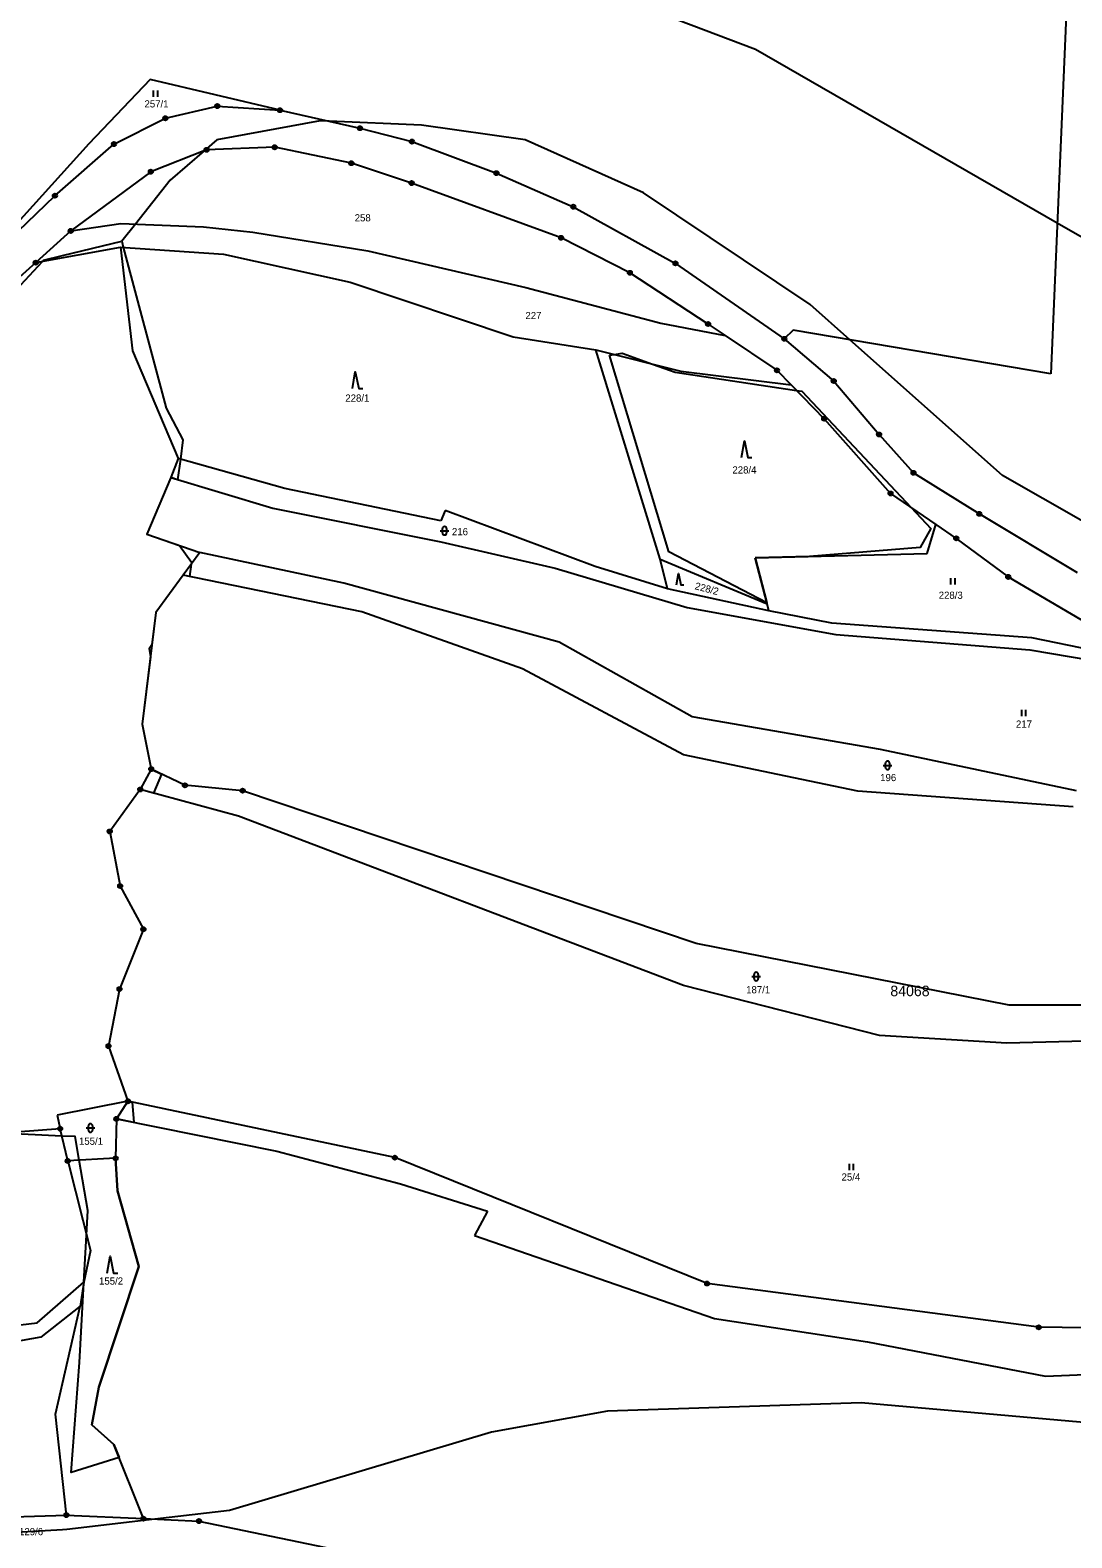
# Model space of a CAD drawing. Extents: x -547623 to -538651, y -1096714 to -1086522.
# Drawn here: x -543757.7 to -543511.1, y -1092763 to -1092406 of the extents above; entities that cross this region are included whole.
import ezdxf

# ---------------------------------------------------------------- set-up
doc = ezdxf.new("R2010")
doc.units = 0
for name, color, linetype in [('Vrstva 1', 7, 'Continuous'), ('Vrstva 25', 7, 'Continuous'), ('Vrstva 52', 7, 'Continuous'), ('Vrstva 53', 7, 'Continuous'), ('Vrstva 83', 7, 'Continuous'), ('Vrstva 86', 7, 'Continuous')]:
    doc.layers.add(name, color=color, linetype=linetype)

msp = doc.modelspace()

# ---------------------------------------------------------------- linework, layer by layer
at = {"layer": 'Vrstva 1'}
for points in [[(-543511.22, -1092374.73), (-543516.09, -1092487.37)], [(-543729.23, -1092417.67), (-543743.79, -1092432.91)], [(-543698.51, -1092424.97), (-543729.23, -1092417.67)], [(-543737.84, -1092433), (-543725.67, -1092426.88)], [(-543725.67, -1092426.88), (-543713.37, -1092424)], [(-543713.37, -1092424), (-543698.51, -1092424.97)], [(-543698.51, -1092424.97), (-543679.6, -1092429.23)], [(-543679.6, -1092429.23), (-543667.31, -1092432.4)], [(-543743.79, -1092432.91), (-543768.17, -1092459.86)], [(-543751.81, -1092445.22), (-543737.84, -1092433)], [(-543715.93, -1092434.35), (-543729.12, -1092439.55)], [(-543699.77, -1092433.74), (-543715.93, -1092434.35)], [(-543681.63, -1092437.52), (-543699.77, -1092433.74)], [(-543667.31, -1092432.4), (-543647.3, -1092439.87)], [(-543667.39, -1092442.23), (-543681.63, -1092437.52)], [(-543729.12, -1092439.55), (-543748.07, -1092453.55)], [(-543647.3, -1092439.87), (-543629.11, -1092447.83)], [(-543631.99, -1092455.19), (-543667.39, -1092442.23)], [(-543764.91, -1092457.77), (-543751.81, -1092445.22)], [(-543629.11, -1092447.83), (-543604.92, -1092461.24)], [(-543748.07, -1092453.55), (-543736.18, -1092451.79)], [(-543736.18, -1092451.79), (-543716.61, -1092452.6)], [(-543748.07, -1092453.55), (-543756.35, -1092461.06)], [(-543716.61, -1092452.6), (-543704.98, -1092453.84)], [(-543704.98, -1092453.84), (-543677.77, -1092458.24)], [(-543615.72, -1092463.47), (-543631.99, -1092455.19)], [(-543756.35, -1092461.06), (-543736.26, -1092457.38)], [(-543736.26, -1092457.38), (-543711.9, -1092459.05)], [(-543736.26, -1092457.38), (-543733.41, -1092481.95)], [(-543711.9, -1092459.05), (-543681.93, -1092465.69)], [(-543677.77, -1092458.24), (-543640.32, -1092466.93)], [(-543756.35, -1092461.06), (-543763.37, -1092467.31)], [(-543604.92, -1092461.24), (-543579.16, -1092479.1)], [(-543681.93, -1092465.69), (-543643.31, -1092478.62)], [(-543597.2, -1092475.6), (-543615.72, -1092463.47)], [(-543640.32, -1092466.93), (-543608.39, -1092475.36)], [(-543608.39, -1092475.36), (-543593.18, -1092478.3)], [(-543597.2, -1092475.6), (-543593.18, -1092478.3)], [(-543577.09, -1092477.06), (-543579.16, -1092479.1)], [(-543516.09, -1092487.37), (-543577.09, -1092477.06)], [(-543643.31, -1092478.62), (-543623.75, -1092481.71)], [(-543593.18, -1092478.3), (-543580.89, -1092486.56)], [(-543579.16, -1092479.1), (-543567.46, -1092489.1)], [(-543733.41, -1092481.95), (-543722.64, -1092507.43)], [(-543623.75, -1092481.71), (-543603.64, -1092486.76)], [(-543608.58, -1092531.29), (-543623.75, -1092481.71)], [(-543603.64, -1092486.76), (-543577.51, -1092490.02)], [(-543580.89, -1092486.56), (-543577.51, -1092490.02)], [(-543577.51, -1092490.02), (-543569.73, -1092498.01)], [(-543567.46, -1092489.1), (-543556.72, -1092501.75)], [(-543569.73, -1092498.01), (-543554.01, -1092515.72)], [(-543556.72, -1092501.75), (-543548.58, -1092510.82)], [(-543722.64, -1092507.43), (-543724.39, -1092511.97)], [(-543697.41, -1092514.51), (-543722.64, -1092507.43)], [(-543724.39, -1092511.97), (-543730.09, -1092525.34)], [(-543724.39, -1092511.97), (-543700.2, -1092519.18)], [(-543548.58, -1092510.82), (-543532.99, -1092520.55)], [(-543660.49, -1092522.2), (-543697.41, -1092514.51)], [(-543554.01, -1092515.72), (-543543.25, -1092523.07)], [(-543700.2, -1092519.18), (-543660.46, -1092527.14)], [(-543659.4, -1092519.77), (-543660.49, -1092522.2)], [(-543623.94, -1092533.02), (-543659.4, -1092519.77)], [(-543545.38, -1092529.97), (-543543.25, -1092523.07)], [(-543543.25, -1092523.07), (-543538.45, -1092526.35)], [(-543532.99, -1092520.55), (-543509.87, -1092534.42)], [(-543730.09, -1092525.34), (-543717.52, -1092529.66)], [(-543660.46, -1092527.14), (-543633.42, -1092533.43)], [(-543538.45, -1092526.35), (-543526.15, -1092535.48)], [(-543717.52, -1092529.66), (-543721.47, -1092535.1)], [(-543683.42, -1092536.97), (-543717.52, -1092529.66)], [(-543586.02, -1092530.97), (-543545.38, -1092529.97)], [(-543633.42, -1092533.43), (-543602.16, -1092542.72)], [(-543606.77, -1092538.33), (-543623.94, -1092533.02)], [(-543608.58, -1092531.29), (-543583.21, -1092541.88)], [(-543606.77, -1092538.33), (-543608.58, -1092531.29)], [(-543583.21, -1092541.88), (-543586.02, -1092530.97)], [(-543721.47, -1092535.1), (-543727.92, -1092543.9)], [(-543679.15, -1092543.78), (-543721.47, -1092535.1)], [(-543632.47, -1092550.94), (-543683.42, -1092536.97)], [(-543526.15, -1092535.48), (-543491.37, -1092555.91)], [(-543582.79, -1092543.52), (-543606.77, -1092538.33)], [(-543727.92, -1092543.9), (-543731.17, -1092570.31)], [(-543641.15, -1092557.25), (-543679.15, -1092543.78)], [(-543602.16, -1092542.72), (-543566.98, -1092549.09)], [(-543582.79, -1092543.52), (-543583.21, -1092541.88)], [(-543567.93, -1092546.42), (-543582.79, -1092543.52)], [(-543520.58, -1092549.87), (-543567.93, -1092546.42)], [(-543600.94, -1092568.62), (-543632.47, -1092550.94)], [(-543566.98, -1092549.09), (-543521.04, -1092552.77)], [(-543491.37, -1092555.91), (-543520.58, -1092549.87)], [(-543521.04, -1092552.77), (-543487.96, -1092558.35)], [(-543603.04, -1092577.63), (-543641.15, -1092557.25)], [(-543556.36, -1092576.35), (-543600.94, -1092568.62)], [(-543731.17, -1092570.31), (-543729.02, -1092580.98)], [(-543510.01, -1092586.1), (-543556.36, -1092576.35)], [(-543561.79, -1092586.19), (-543603.04, -1092577.63)], [(-543729.02, -1092580.98), (-543731.63, -1092585.8)], [(-543721.04, -1092584.81), (-543729.02, -1092580.98)], [(-543731.63, -1092585.8), (-543738.83, -1092595.74)], [(-543708.37, -1092592.09), (-543731.63, -1092585.8)], [(-543707.39, -1092586.09), (-543721.04, -1092584.81)], [(-543600.04, -1092622.29), (-543707.39, -1092586.09)], [(-543510.77, -1092589.92), (-543561.79, -1092586.19)], [(-543603.03, -1092632.2), (-543708.37, -1092592.09)], [(-543738.83, -1092595.74), (-543736.38, -1092608.66)], [(-543736.38, -1092608.66), (-543730.86, -1092618.88)], [(-543730.86, -1092618.88), (-543736.53, -1092633.08)], [(-543525.96, -1092636.91), (-543600.04, -1092622.29)], [(-543736.53, -1092633.08), (-543739.14, -1092646.56)], [(-543556.63, -1092644.05), (-543603.03, -1092632.2)], [(-543507.94, -1092636.84), (-543525.96, -1092636.91)], [(-543526.5, -1092645.9), (-543556.63, -1092644.05)], [(-543739.14, -1092646.56), (-543734.54, -1092659.62)], [(-543508.02, -1092645.37), (-543526.5, -1092645.9)], [(-543734.54, -1092659.62), (-543751.31, -1092662.9)], [(-543751.31, -1092662.9), (-543750.57, -1092666.13)], [(-543734.54, -1092659.62), (-543737.27, -1092663.8)], [(-543671.35, -1092672.97), (-543734.54, -1092659.62)], [(-543750.57, -1092666.13), (-543791.26, -1092669.21)], [(-543748.77, -1092673.75), (-543750.57, -1092666.13)], [(-543737.27, -1092663.8), (-543737.44, -1092673.13)], [(-543737.27, -1092663.8), (-543699.31, -1092671.45)], [(-543737.44, -1092673.13), (-543748.77, -1092673.75)], [(-543737, -1092680.86), (-543737.44, -1092673.13)], [(-543699.31, -1092671.45), (-543669.99, -1092679.16)], [(-543597.43, -1092702.78), (-543671.35, -1092672.97)], [(-543748.77, -1092673.75), (-543743.39, -1092694.98)], [(-543669.99, -1092679.16), (-543649.42, -1092685.65)], [(-543731.94, -1092698.78), (-543737, -1092680.86)], [(-543649.42, -1092685.65), (-543652.5, -1092691.44)], [(-543652.5, -1092691.44), (-543595.66, -1092711.03)], [(-543743.39, -1092694.98), (-543744.93, -1092702.47)], [(-543741.42, -1092727.31), (-543731.94, -1092698.78)], [(-543756.05, -1092712.1), (-543744.93, -1092702.47)], [(-543744.93, -1092702.47), (-543745.87, -1092708.11)], [(-543518.91, -1092713.14), (-543597.43, -1092702.78)], [(-543745.87, -1092708.11), (-543755.12, -1092715.47)], [(-543751.69, -1092733.73), (-543745.87, -1092708.11)], [(-543801.65, -1092717.55), (-543756.05, -1092712.1)], [(-543595.66, -1092711.03), (-543559.44, -1092716.61)], [(-543755.12, -1092715.47), (-543793.17, -1092722.29)], [(-543469.07, -1092713.85), (-543518.91, -1092713.14)], [(-543559.44, -1092716.61), (-543517.32, -1092724.75)], [(-543517.32, -1092724.75), (-543474.01, -1092722.86)], [(-543743.08, -1092736.25), (-543741.42, -1092727.31)], [(-543749.08, -1092757.6), (-543751.69, -1092733.73)], [(-543737.84, -1092740.87), (-543743.08, -1092736.25)], [(-543730.85, -1092758.45), (-543737.84, -1092740.87)], [(-543802.04, -1092759.3), (-543749.08, -1092757.6)], [(-543749.08, -1092757.6), (-543730.85, -1092758.45)], [(-543730.85, -1092758.45), (-543717.71, -1092759.02)], [(-543717.71, -1092759.02), (-543683.48, -1092766.12)]]:
    msp.add_lwpolyline(points, dxfattribs=at)
at = {"layer": 'Vrstva 25'}
for p, q in [((-543728.46, -1092421.81), (-543728.46, -1092420.31)), ((-543727.46, -1092421.81), (-543727.46, -1092420.31)), ((-543660.59, -1092524.54), (-543658.59, -1092524.54)), ((-543660.09, -1092525.04), (-543660.09, -1092524.04)), ((-543659.09, -1092524.04), (-543659.09, -1092525.04)), ((-543539.73, -1092537.29), (-543539.73, -1092535.79)), ((-543538.73, -1092537.29), (-543538.73, -1092535.79)), ((-543522.96, -1092568.43), (-543522.96, -1092566.93)), ((-543521.96, -1092568.43), (-543521.96, -1092566.93)), ((-543555.72, -1092580.09), (-543553.72, -1092580.09)), ((-543555.22, -1092580.59), (-543555.22, -1092579.59)), ((-543554.22, -1092579.59), (-543554.22, -1092580.59)), ((-543586.82, -1092630.09), (-543584.82, -1092630.09)), ((-543586.32, -1092630.59), (-543586.32, -1092629.59)), ((-543585.32, -1092629.59), (-543585.32, -1092630.59)), ((-543744.4, -1092665.95), (-543742.4, -1092665.95)), ((-543743.9, -1092666.45), (-543743.9, -1092665.45)), ((-543742.9, -1092665.45), (-543742.9, -1092666.45)), ((-543563.74, -1092675.9), (-543563.74, -1092674.4)), ((-543562.74, -1092675.9), (-543562.74, -1092674.4))]:
    msp.add_line(p, q, dxfattribs=at)
for points in [[(-543681.41, -1092490.9), (-543680.71, -1092486.9), (-543679.91, -1092490.9), (-543678.91, -1092490.9)], [(-543589.32, -1092507.23), (-543588.62, -1092503.23), (-543587.82, -1092507.23), (-543586.82, -1092507.23)], [(-543604.65, -1092537.35), (-543604.18, -1092534.67), (-543603.64, -1092537.35), (-543602.97, -1092537.35)], [(-543739.44, -1092700.33), (-543738.74, -1092696.33), (-543737.94, -1092700.33), (-543736.94, -1092700.33)]]:
    msp.add_lwpolyline(points, dxfattribs=at)
for centre, start, end in [((-543659.59, -1092524.04), 0, 180), ((-543659.59, -1092525.04), 180, 0), ((-543554.72, -1092579.59), 0, 180), ((-543554.72, -1092580.59), 180, 0), ((-543585.82, -1092629.59), 0, 180), ((-543585.82, -1092630.59), 180, 0), ((-543743.4, -1092665.45), 0, 180), ((-543743.4, -1092666.45), 180, 0)]:
    msp.add_arc(centre, 0.5, start, end, dxfattribs=at)
at = {"layer": 'Vrstva 52'}
for points in [[(-543665, -1092380.5), (-543586, -1092410.5), (-543514.54, -1092451.62), (-543496.5, -1092462), (-543452.5, -1092480.5), (-543361.5, -1092507.5), (-543304.5, -1092517), (-543251.5, -1092517), (-543221.5, -1092511.5), (-543183, -1092496.5), (-543163, -1092486), (-543137, -1092463.5), (-543128.5, -1092445.5), (-543127.82, -1092431.2), (-543127.48, -1092424.11), (-543126.01, -1092393.13)], [(-543563.64, -1092479.33), (-543573, -1092471), (-543612.5, -1092444.5), (-543640.5, -1092432), (-543665, -1092428.5), (-543686.89, -1092427.59), (-543689, -1092427.5), (-543713.5, -1092432), (-543716.47, -1092434.56), (-543724.5, -1092441.5), (-543732.77, -1092451.93), (-543736, -1092456)], [(-543917, -1092752), (-543914.39, -1092748.52), (-543912.35, -1092746.73), (-543912.4, -1092745.86), (-543897.5, -1092725), (-543883.5, -1092702), (-543877, -1092678), (-543872.5, -1092669.5), (-543870, -1092660.5), (-543852.5, -1092615.5), (-543845.5, -1092609), (-543844.84, -1092606.69), (-543844.76, -1092606.41), (-543844.6, -1092605.86), (-543843.5, -1092602), (-543823.5, -1092557), (-543781.5, -1092489.5), (-543754.75, -1092460.77), (-543754.5, -1092460.5), (-543750, -1092459.41), (-543736, -1092456)], [(-543736, -1092456), (-543735.62, -1092457.42), (-543725.5, -1092495.5), (-543721.5, -1092503), (-543722.12, -1092507.57)], [(-543193, -1092818.5), (-543194.6, -1092788.49), (-543195.1, -1092778.98), (-543195.5, -1092771.5), (-543204.5, -1092741.5), (-543233, -1092709.5), (-543286.24, -1092664.3), (-543303.98, -1092649.23), (-543312.5, -1092642), (-543357.5, -1092615), (-543393.5, -1092592.22), (-543397, -1092590), (-543405.16, -1092583.68), (-543417, -1092574.5), (-543432.97, -1092565.39), (-543443.8, -1092559.22), (-543527.5, -1092511.5), (-543563.64, -1092479.33)], [(-543620.5, -1092483), (-543619.37, -1092482.81), (-543617.5, -1092482.5), (-543610.34, -1092485.08), (-543605, -1092487), (-543576.25, -1092491.31), (-543575, -1092491.5), (-543549.16, -1092519.03), (-543544.5, -1092524), (-543547, -1092528.5), (-543573.22, -1092530.66), (-543586.02, -1092530.97)], [(-543586.02, -1092530.97), (-543583.28, -1092541.59), (-543606.5, -1092529.5), (-543620.5, -1092483)], [(-543722.12, -1092507.57), (-543722.79, -1092512.45), (-543724.39, -1092511.97), (-543730.09, -1092525.34), (-543722.36, -1092528), (-543719.5, -1092532), (-543719.57, -1092532.48), (-543719.99, -1092535.4), (-543721.47, -1092535.1), (-543727.92, -1092543.9), (-543728.86, -1092551.54), (-543729.5, -1092552.5), (-543729.22, -1092554.42), (-543731.17, -1092570.31), (-543729.02, -1092580.98), (-543726.6, -1092582.14), (-543728.47, -1092586.66), (-543731.63, -1092585.8), (-543738.83, -1092595.74), (-543736.38, -1092608.66), (-543730.86, -1092618.88), (-543736.53, -1092633.08), (-543739.14, -1092646.56), (-543734.54, -1092659.62), (-543733.52, -1092659.84), (-543733.11, -1092664.64), (-543737.27, -1092663.8), (-543737.44, -1092673.13), (-543737, -1092680.86), (-543731.94, -1092698.78), (-543741.42, -1092727.31), (-543743.08, -1092736.25), (-543737.84, -1092740.87), (-543736.62, -1092743.94), (-543748, -1092747.5), (-543746, -1092721.5), (-543744.95, -1092702.58), (-543744.94, -1092702.48), (-543744.32, -1092691.3), (-543744, -1092685.5), (-543746.04, -1092673.6), (-543747, -1092668), (-543750, -1092667.86), (-543750.16, -1092667.85), (-543764.46, -1092667.18)], [(-543243, -1092767), (-543278.5, -1092756), (-543561, -1092731), (-543621, -1092733), (-543648.5, -1092738), (-543710.5, -1092756.5), (-543728.18, -1092758.57), (-543749, -1092761), (-543750, -1092761.06), (-543830.91, -1092765.72), (-543844.5, -1092766.5)]]:
    msp.add_lwpolyline(points, dxfattribs=at)
at = {"layer": 'Vrstva 83'}
for centre, radius in [((-543713.37, -1092424), 0.5), ((-543725.67, -1092426.88), 0.5), ((-543725.67, -1092426.88), 0.1), ((-543713.37, -1092424), 0.1), ((-543698.51, -1092424.97), 0.5), ((-543698.51, -1092424.97), 0.1), ((-543679.6, -1092429.23), 0.5), ((-543679.6, -1092429.23), 0.1), ((-543737.84, -1092433), 0.5), ((-543737.84, -1092433), 0.1), ((-543715.93, -1092434.35), 0.5), ((-543715.93, -1092434.35), 0.1), ((-543699.77, -1092433.74), 0.5), ((-543699.77, -1092433.74), 0.1), ((-543667.31, -1092432.4), 0.5), ((-543667.31, -1092432.4), 0.1), ((-543681.63, -1092437.52), 0.5), ((-543681.63, -1092437.52), 0.1), ((-543729.12, -1092439.55), 0.5), ((-543729.12, -1092439.55), 0.1), ((-543647.3, -1092439.87), 0.5), ((-543647.3, -1092439.87), 0.1), ((-543751.81, -1092445.22), 0.5), ((-543751.81, -1092445.22), 0.1), ((-543667.39, -1092442.23), 0.5), ((-543667.39, -1092442.23), 0.1), ((-543629.11, -1092447.83), 0.5), ((-543629.11, -1092447.83), 0.1), ((-543748.07, -1092453.55), 0.5), ((-543748.07, -1092453.55), 0.1), ((-543631.99, -1092455.19), 0.5), ((-543631.99, -1092455.19), 0.1), ((-543756.35, -1092461.06), 0.5), ((-543756.35, -1092461.06), 0.1), ((-543615.72, -1092463.47), 0.5), ((-543604.92, -1092461.24), 0.5), ((-543604.92, -1092461.24), 0.1), ((-543615.72, -1092463.47), 0.1), ((-543597.2, -1092475.6), 0.5), ((-543597.2, -1092475.6), 0.1), ((-543579.16, -1092479.1), 0.5), ((-543579.16, -1092479.1), 0.1), ((-543580.89, -1092486.56), 0.5), ((-543580.89, -1092486.56), 0.1), ((-543567.46, -1092489.1), 0.5), ((-543567.46, -1092489.1), 0.1), ((-543569.73, -1092498.01), 0.5), ((-543569.73, -1092498.01), 0.1), ((-543556.72, -1092501.75), 0.5), ((-543556.72, -1092501.75), 0.1), ((-543548.58, -1092510.82), 0.5), ((-543548.58, -1092510.82), 0.1), ((-543554.01, -1092515.72), 0.5), ((-543554.01, -1092515.72), 0.1), ((-543532.99, -1092520.55), 0.5), ((-543532.99, -1092520.55), 0.1), ((-543538.45, -1092526.35), 0.5), ((-543538.45, -1092526.35), 0.1), ((-543526.15, -1092535.48), 0.5), ((-543526.15, -1092535.48), 0.1), ((-543729.02, -1092580.98), 0.5), ((-543729.02, -1092580.98), 0.1), ((-543721.04, -1092584.81), 0.5), ((-543731.63, -1092585.8), 0.5), ((-543731.63, -1092585.8), 0.1), ((-543721.04, -1092584.81), 0.1), ((-543707.39, -1092586.09), 0.5), ((-543707.39, -1092586.09), 0.1), ((-543738.83, -1092595.74), 0.5), ((-543738.83, -1092595.74), 0.1), ((-543736.38, -1092608.66), 0.5), ((-543736.38, -1092608.66), 0.1), ((-543730.86, -1092618.88), 0.5), ((-543730.86, -1092618.88), 0.1), ((-543736.53, -1092633.08), 0.5), ((-543736.53, -1092633.08), 0.1), ((-543739.14, -1092646.56), 0.5), ((-543739.14, -1092646.56), 0.1), ((-543734.54, -1092659.62), 0.5), ((-543734.54, -1092659.62), 0.1), ((-543750.57, -1092666.13), 0.5), ((-543750.57, -1092666.13), 0.1), ((-543737.27, -1092663.8), 0.5), ((-543737.27, -1092663.8), 0.1), ((-543748.77, -1092673.75), 0.5), ((-543737.44, -1092673.13), 0.5), ((-543737.44, -1092673.13), 0.1), ((-543671.35, -1092672.97), 0.5), ((-543671.35, -1092672.97), 0.1), ((-543748.77, -1092673.75), 0.1), ((-543597.43, -1092702.78), 0.5), ((-543597.43, -1092702.78), 0.1), ((-543518.91, -1092713.14), 0.5), ((-543518.91, -1092713.14), 0.1), ((-543749.08, -1092757.6), 0.5), ((-543749.08, -1092757.6), 0.1), ((-543730.85, -1092758.45), 0.5), ((-543730.85, -1092758.45), 0.1), ((-543717.71, -1092759.02), 0.5), ((-543717.71, -1092759.02), 0.1)]:
    msp.add_circle(centre, radius, dxfattribs=at)

# ---------------------------------------------------------------- texts
at = {"layer": 'Vrstva 53'}
msp.add_text('84068', height=2.5, dxfattribs=at).set_placement((-543554.06, -1092634.75))
at = {"layer": 'Vrstva 86'}
for s, p in [('257/1', (-543730.61, -1092424.32)), ('258', (-543680.85, -1092451.3)), ('227', (-543640.44, -1092474.44)), ('228/1', (-543683.07, -1092493.98)), ('228/4', (-543591.44, -1092510.99)), ('216', (-543657.83, -1092525.61)), ('228/3', (-543542.61, -1092540.66)), ('217', (-543524.32, -1092571.17)), ('196', (-543556.46, -1092583.83)), ('187/1', (-543588.19, -1092634.06)), ('155/1', (-543746.12, -1092669.93)), ('25/4', (-543565.6, -1092678.41)), ('155/2', (-543741.37, -1092703.03)), ('129/6', (-543760.3, -1092762.37))]:
    msp.add_text(s, height=1.7, dxfattribs=at).set_placement(p)
msp.add_text('228/2', height=1.7, rotation=345.1643, dxfattribs=at).set_placement((-543600.46, -1092538.36))

doc.saveas('drawing.dxf')
